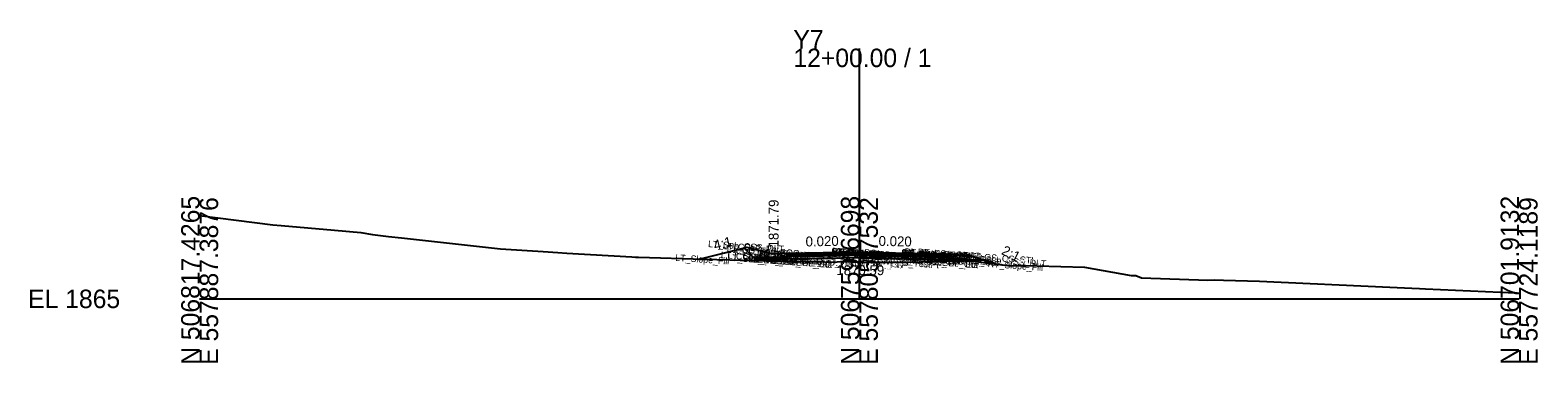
# Model space of a CAD drawing. Extents: x -26 to 557959, y -10 to 506992.
# Drawn here: x -25.7 to 202.8, y 1990.3 to 2040.7 of the extents above; entities that cross this region are included whole.
import ezdxf

# ---------------------------------------------------------------- set-up
doc = ezdxf.new("R2010")
doc.units = 0
for name, color, linetype in [('Default', 7, 'Continuous'), ('Exist Cross Section Cell', 7, 'Continuous'), ('Exist XS Center Line Elevation Label', 7, 'Continuous'), ('Exist XS Ground Line', 7, 'Continuous'), ('Prop CMT Conc Surface', 7, 'Continuous'), ('Prop CMT Concrete Structures', 7, 'Continuous'), ('Prop CMT Pvmt Course 1', 7, 'Continuous'), ('Prop CMT Pvmt Course 1 CG', 7, 'Continuous'), ('Prop CMT Pvmt Course 1 Wedge', 7, 'Continuous'), ('Prop CMT Pvmt Course 2', 7, 'Continuous'), ('Prop CMT Pvmt Course 2 Wedge', 7, 'Continuous'), ('Prop CMT Pvmt Course 3', 7, 'Continuous'), ('Prop CMT Pvmt Course 3 Wedge', 7, 'Continuous'), ('Prop CMT Pvmt Surface', 7, 'Continuous'), ('Prop CMT Pvmt Surface Shoulder', 7, 'Continuous'), ('Prop CMT Pvmt Wedge Surface 1', 7, 'Continuous'), ('Prop CMT Pvmt Wedge Surface 2', 7, 'Continuous'), ('Prop CMT Pvmt Wedge Surface 3', 7, 'Continuous'), ('Prop CMT Shld Paved Course 1', 7, 'Continuous'), ('Prop CMT Shld Paved Course 2', 7, 'Continuous'), ('Prop CMT Shld Paved Course 3', 7, 'Continuous'), ('Prop CMT Slope Grass', 7, 'Continuous'), ('Prop CMT Subgrade Earthwork', 7, 'Continuous'), ('Prop XS Earthwork Shape', 7, 'Continuous'), ('Prop XS Hydro Elevations', 7, 'Continuous'), ('Prop XS SE Text', 7, 'Continuous'), ('Prop XS Side Slope Text', 7, 'Continuous'), ('Typical Text Asphalt at Bridge Approach CELL', 7, 'Continuous')]:
    doc.layers.add(name, color=color, linetype=linetype)

msp = doc.modelspace()

# ---------------------------------------------------------------- linework, layer by layer
at = {"layer": 'Exist Cross Section Cell'}
for p, q in [((100, 2000), (100, 2037.91)), ((0, 2000), (100, 2000)), ((100, 2000), (200, 2000))]:
    msp.add_line(p, q, dxfattribs=at)
at = {"layer": 'Exist XS Ground Line'}
for p, q in [((0, 2012.64), (11.09, 2011.21)), ((11.09, 2011.21), (12.35, 2011.13)), ((12.35, 2011.13), (20.43, 2010.4)), ((20.43, 2010.4), (24.44, 2010.05)), ((24.44, 2010.05), (26.19, 2009.77)), ((26.19, 2009.77), (28.6, 2009.44)), ((28.6, 2009.44), (30.59, 2009.25)), ((30.59, 2009.25), (45.61, 2007.6)), ((45.61, 2007.6), (52.09, 2007.18)), ((52.09, 2007.18), (54.28, 2007.01)), ((54.28, 2007.01), (55.66, 2006.9)), ((55.66, 2006.9), (65.5, 2006.38)), ((65.5, 2006.38), (66.08, 2006.34)), ((66.08, 2006.34), (66.5, 2006.33)), ((66.5, 2006.33), (76.47, 2005.99)), ((76.47, 2005.99), (82.27, 2005.84)), ((82.27, 2005.84), (89.37, 2005.65)), ((89.37, 2005.65), (89.84, 2005.65)), ((89.84, 2005.65), (91.35, 2005.61)), ((91.35, 2005.61), (93.66, 2005.68)), ((93.66, 2005.68), (95.8, 2005.57)), ((95.8, 2005.57), (97.46, 2005.65)), ((97.46, 2005.65), (98.68, 2005.61)), ((98.68, 2005.61), (100, 2005.59)), ((100, 2005.59), (100.3, 2005.58)), ((100.3, 2005.58), (107.46, 2005.58)), ((107.46, 2005.58), (111.72, 2005.64)), ((111.72, 2005.64), (116.49, 2005.8)), ((116.49, 2005.8), (119.24, 2005.47)), ((119.24, 2005.47), (122.51, 2005.07)), ((122.51, 2005.07), (126.97, 2004.99)), ((126.97, 2004.99), (134.11, 2004.78)), ((134.11, 2004.78), (141.22, 2003.54)), ((141.22, 2003.54), (141.89, 2003.56)), ((141.89, 2003.56), (142.76, 2003.21)), ((142.76, 2003.21), (152.82, 2002.84)), ((152.82, 2002.84), (153.88, 2002.9)), ((153.88, 2002.9), (155.21, 2002.83)), ((155.21, 2002.83), (160.67, 2002.69)), ((160.67, 2002.69), (180.39, 2001.78)), ((180.39, 2001.78), (183.74, 2001.64)), ((183.74, 2001.64), (184.89, 2001.56)), ((184.89, 2001.56), (185.82, 2001.5)), ((185.82, 2001.5), (199.45, 2000.93)), ((199.45, 2000.93), (200, 2000.85))]:
    msp.add_line(p, q, dxfattribs=at)
at = {"layer": 'Prop CMT Conc Surface'}
msp.add_lwpolyline([(89, 2006.87), (87, 2006.79), (85, 2007.29)], dxfattribs=at)
at = {"layer": 'Prop CMT Concrete Structures'}
for points in [[(89, 2006.87), (87, 2006.79), (85, 2007.29)], [(85, 2007.29), (85, 2006.29)], [(89, 2006.29), (89, 2006.87)], [(85, 2006.29), (87, 2006.29), (89, 2006.29)]]:
    msp.add_lwpolyline(points, dxfattribs=at)
at = {"layer": 'Prop CMT Pvmt Course 1'}
for points in [[(100, 2007.09), (89, 2006.87)], [(89, 2006.75), (100, 2006.97)], [(89, 2006.87), (89, 2006.62), (89, 2006.62), (89, 2006.75)], [(100, 2006.84), (100, 2007.09)], [(100, 2007.09), (111, 2006.87)], [(100, 2006.84), (100, 2007.09)], [(100, 2006.97), (100, 2006.84), (100, 2006.84)], [(111, 2006.75), (100, 2006.97)], [(100, 2006.97), (100, 2006.84), (100, 2006.84)], [(111, 2006.87), (111, 2006.62), (111, 2006.62), (111, 2006.75)]]:
    msp.add_lwpolyline(points, dxfattribs=at)
at = {"layer": 'Prop CMT Pvmt Course 1 CG'}
for points in [[(89, 2006.29), (84.5, 2006.29), (84.21, 2006)], [(84.21, 2006), (89, 2006)], [(89, 2006), (89, 2006.29)]]:
    msp.add_lwpolyline(points, dxfattribs=at)
at = {"layer": 'Prop CMT Pvmt Course 1 Wedge'}
for points in [[(100, 2006.97), (89, 2006.75)], [(100, 2006.97), (111, 2006.75)]]:
    msp.add_lwpolyline(points, dxfattribs=at)
at = {"layer": 'Prop CMT Pvmt Course 2'}
for points in [[(89, 2006.37), (89, 2006.37), (89, 2006.62), (89, 2006.62)], [(89, 2006.62), (89, 2006.37)], [(111, 2006.37), (111, 2006.37), (111, 2006.62), (111, 2006.62)], [(111, 2006.62), (111, 2006.37)]]:
    msp.add_lwpolyline(points, dxfattribs=at)
at = {"layer": 'Prop CMT Pvmt Course 2 Wedge'}
for points in [[(100, 2006.84), (89, 2006.62)], [(100, 2006.84), (111, 2006.62)]]:
    msp.add_lwpolyline(points, dxfattribs=at)
at = {"layer": 'Prop CMT Pvmt Course 3'}
for points in [[(89, 2006.37), (89, 2006.37), (89, 2006), (89, 2006)], [(89, 2006), (89, 2006.37)], [(111, 2006.37), (111, 2006.37), (111, 2006), (111, 2006)], [(111, 2006), (111, 2006.37)]]:
    msp.add_lwpolyline(points, dxfattribs=at)
at = {"layer": 'Prop CMT Pvmt Course 3 Wedge'}
for points in [[(100, 2006.59), (89, 2006.37)], [(100, 2006.59), (111, 2006.37)]]:
    msp.add_lwpolyline(points, dxfattribs=at)
at = {"layer": 'Prop CMT Pvmt Surface'}
msp.add_line((100, 2007.09), (113, 2006.83), dxfattribs=at)
msp.add_lwpolyline([(100, 2007.09), (89, 2006.87)], dxfattribs=at)
at = {"layer": 'Prop CMT Pvmt Surface Shoulder'}
msp.add_lwpolyline([(89, 2006.87), (89, 2006.87)], dxfattribs=at)
at = {"layer": 'Prop CMT Pvmt Wedge Surface 1'}
for points in [[(100, 2006.97), (89, 2006.75)], [(89, 2006.62), (89, 2006.87)], [(89, 2006.75), (89, 2006.62), (89, 2006.62)], [(100, 2006.97), (111, 2006.75)], [(111, 2006.62), (111, 2006.87)], [(111, 2006.75), (111, 2006.62), (111, 2006.62)]]:
    msp.add_lwpolyline(points, dxfattribs=at)
at = {"layer": 'Prop CMT Pvmt Wedge Surface 2'}
for points in [[(89, 2006.62), (89, 2006.87)], [(100, 2006.84), (89, 2006.62)], [(100, 2006.84), (111, 2006.62)], [(111, 2006.62), (111, 2006.87)]]:
    msp.add_lwpolyline(points, dxfattribs=at)
at = {"layer": 'Prop CMT Pvmt Wedge Surface 3'}
for points in [[(89, 2006.37), (89, 2006.87)], [(100, 2006.59), (89, 2006.37)], [(100, 2006.59), (111, 2006.37)], [(111, 2006.37), (111, 2006.87)]]:
    msp.add_lwpolyline(points, dxfattribs=at)
at = {"layer": 'Prop CMT Shld Paved Course 1'}
for points in [[(89, 2006.87), (89, 2006.87), (89, 2006.62), (89, 2006.62)], [(89, 2006.62), (89, 2006.87)], [(111, 2006.87), (113, 2006.83), (113.26, 2006.58)], [(111, 2006.62), (111, 2006.87)], [(113.26, 2006.58), (111, 2006.62)]]:
    msp.add_lwpolyline(points, dxfattribs=at)
at = {"layer": 'Prop CMT Shld Paved Course 2'}
for points in [[(89, 2006.62), (89, 2006.62), (89, 2006.37), (89, 2006.37)], [(89, 2006.37), (89, 2006.62)], [(111, 2006.62), (113.26, 2006.58), (113.51, 2006.32)], [(111, 2006.37), (111, 2006.62)], [(113.51, 2006.32), (111, 2006.37)]]:
    msp.add_lwpolyline(points, dxfattribs=at)
at = {"layer": 'Prop CMT Shld Paved Course 3'}
for points in [[(89, 2006.37), (89, 2006.37), (89, 2006), (89, 2006)], [(89, 2006), (89, 2006.37)], [(111, 2006.37), (113.51, 2006.32), (114.01, 2006.31), (114.39, 2005.93)], [(111, 2006), (111, 2006.37)], [(114.39, 2005.93), (111, 2006)]]:
    msp.add_lwpolyline(points, dxfattribs=at)
at = {"layer": 'Prop CMT Slope Grass'}
for p, q in [((113, 2006.83), (117, 2006.51)), ((117, 2006.51), (120.65, 2005.3))]:
    msp.add_line(p, q, dxfattribs=at)
msp.add_lwpolyline([(85, 2007.29), (83, 2007.79), (75.87, 2006.01)], dxfattribs=at)
at = {"layer": 'Prop CMT Subgrade Earthwork'}
msp.add_line((100, 2006.22), (89, 2006), dxfattribs=at)
for points in [[(89, 2006), (84.21, 2006), (82.53, 2007.67)], [(89, 2006), (89, 2006)], [(89, 2006), (89, 2006)], [(100, 2006.22), (114.39, 2005.93)], [(111, 2006), (111, 2006)], [(114.39, 2005.93), (119.03, 2005.84)]]:
    msp.add_lwpolyline(points, dxfattribs=at)
at = {"layer": 'Prop XS Earthwork Shape'}
msp.add_lwpolyline([(91.35, 2005.61), (93.66, 2005.68), (95.8, 2005.57), (97.46, 2005.65), (98.68, 2005.61), (100, 2005.59), (100.3, 2005.58), (107.46, 2005.58), (111.72, 2005.64), (116.49, 2005.8), (119.24, 2005.47), (120.65, 2005.3), (119.03, 2005.84), (114.39, 2005.93), (100, 2006.22), (89, 2006), (84.21, 2006), (82.53, 2007.67), (75.87, 2006.01), (76.47, 2005.99), (82.27, 2005.84), (89.37, 2005.65), (89.84, 2005.65)], close=True, dxfattribs=at)

# ---------------------------------------------------------------- texts
at = {"layer": 'Default'}
msp.add_text('-', height=0.0001, dxfattribs=at).set_placement((0, 2000))
at = {"layer": 'Exist Cross Section Cell'}
for s, p in [('Y7', (90, 2037.91)), ('12+00.00 / 1', (90, 2035.11)), ('EL 1865', (-26, 1998.6))]:
    msp.add_text(s, height=2.8, dxfattribs=at).set_placement(p)
for s, p in [('N 506817.4265', (0, 1990)), ('E 557887.3876', (2.8, 1990)), ('N 506759.6698', (100, 1990)), ('E 557805.7532', (102.8, 1990)), ('N 506701.9132', (200, 1990)), ('E 557724.1189', (202.8, 1990))]:
    msp.add_text(s, height=2.8, rotation=90, dxfattribs=at).set_placement(p)
at = {"layer": 'Exist XS Center Line Elevation Label'}
msp.add_text('1870.59', height=1.5, dxfattribs=at).set_placement((96.51, 2003.59))
at = {"layer": 'Prop XS Hydro Elevations'}
msp.add_text('1871.79', height=1.5, rotation=90, dxfattribs=at).set_placement((87.75, 2007.79))
at = {"layer": 'Prop XS SE Text'}
for rotation, p in [(1.1458, (91.86, 2007.93)), (358.8542, (102.9, 2008.03))]:
    msp.add_text('0.020', height=1.5, rotation=rotation, dxfattribs=at).set_placement(p)
at = {"layer": 'Prop XS Side Slope Text'}
for s, rotation, p in [('4:1', 14.0362, (78.1, 2007.34)), ('2:1', 333.4349, (121.41, 2006.82))]:
    msp.add_text(s, height=1.5, rotation=rotation, dxfattribs=at).set_placement(p)
at = {"layer": 'Typical Text Asphalt at Bridge Approach CELL'}
for s, p in [('LT_Sub_OSS_DLT', (77.04, 2007.85)), ('LT_Slope_Fill', (72.08, 2005.77)), ('LT_CG1_Shelf_Out', (78.97, 2006.17)), ('LT_CSLP_Pnt', (79.27, 2007.55)), ('LT_CG_Top_BOC', (79.88, 2007.15)), ('LT_Sub_OEOP', (79.95, 2005.79)), ('LT_CG_Bot_BOC', (80.02, 2006.13)), ('LT_CG_Top_Gut', (82.16, 2006.63)), ('LT_CG_Bot_Gut', (82.3, 2006.12)), ('LT_Sub_Trench_Out', (83.09, 2005.91)), ('LT_PV_Sub_Tie_Out', (83.16, 2005.57)), ('LT_PV_OEEOP_EG', (83.58, 2005.54)), ('LT_PV2_OEEOP', (84.37, 2006.44)), ('LT_PV3_OEEOP', (84.37, 2006.19)), ('LT_Sub_OEEOP', (84.39, 2005.82)), ('LT_PV1_OEEOP', (84.49, 2006.56)), ('LT_PV2_OEOT', (84.72, 2006.42)), ('LT_PV3_OEOT', (84.72, 2006.17)), ('LT_Sub_OEOT', (84.74, 2005.79)), ('LT_PS2_OEOP', (84.76, 2006.42)), ('LT_PS3_OEOP', (84.76, 2006.17)), ('LT_PV1_OEOT', (84.84, 2006.66)), ('LT_PS1_OEOP', (84.88, 2006.66)), ('LT_CG_Bot_IE', (84.89, 2006.07)), ('RT_PV2_IEEOP', (95.69, 2006.64)), ('RT_PV3_IEEOP', (95.69, 2006.39)), ('LT_PV2_IEEOP', (95.75, 2006.64)), ('LT_PV3_IEEOP', (95.75, 2006.39)), ('RT_PV1_IEEOP', (95.81, 2006.76)), ('LT_PV1_IEEOP', (95.87, 2006.75)), ('PV2_PGL', (97.32, 2006.53)), ('PV1_PGL', (97.44, 2006.77)), ('RT_PV_Sub_Tie_Out', (105.07, 2005.54)), ('RT_PV2_OEEOP', (106.31, 2006.45)), ('RT_PV3_OEEOP', (106.31, 2006.2)), ('RT_Sub_OEEOP', (106.33, 2005.82)), ('RT_PV1_OEEOP', (106.43, 2006.56)), ('RT_PV2_OEOT', (106.66, 2006.42)), ('RT_PV3_OEOT', (106.66, 2006.17)), ('RT_Sub_OEOT', (106.69, 2005.8)), ('RT_PV1_OEOT', (106.78, 2006.67)), ('RT_Sub_Trench_Out', (108.42, 2005.84)), ('RT_PS3_Shelf_Out', (108.59, 2006.19)), ('RT_PS1_OEOP', (108.82, 2006.62)), ('RT_PS2_OEOP', (108.96, 2006.38)), ('RT_PS3_OEOP', (109.21, 2006.12)), ('RT_GS_OS_CTL', (116.38, 2006.01)), ('RT_Sub_OSS_DLT', (116.59, 2005.64)), ('LT_PV_EG_TestPt', (89.52, 2005.48)), ('RT_PV_IEEOP_EG', (94.9, 2005.45)), ('LT_PV_IEEOP_EG', (94.96, 2005.44)), ('RT_PV_EG_TestPt', (100.46, 2005.43)), ('RT_PV_OEEOP_EG', (105.52, 2005.51)), ('RT_Slope_Fill', (119.43, 2004.82))]:
    msp.add_text(s, height=1, rotation=356, dxfattribs=at).set_placement(p)

doc.saveas('drawing.dxf')
